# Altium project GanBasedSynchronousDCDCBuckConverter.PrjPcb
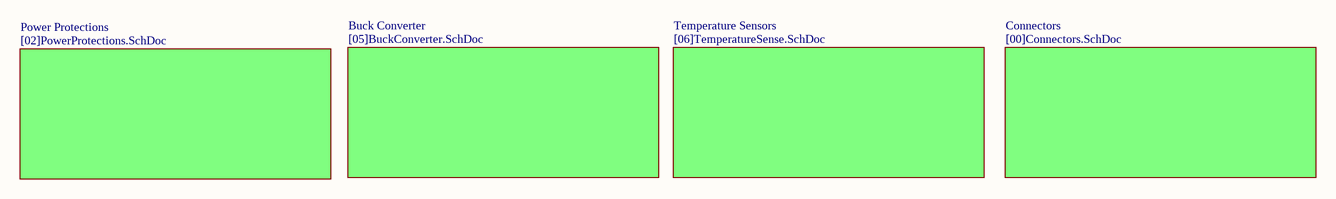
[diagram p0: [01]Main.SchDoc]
5 sheets, 48 parts. Net scope: flat (ports and power ports of the same name join across sheets).
Board file: BuckConverterDesign.PcbDoc
Sheets:
  [01]Main.SchDoc
    Power Protections = [02]PowerProtections.SchDoc
    Buck Converter = [05]BuckConverter.SchDoc
    Temperature Sensors = [06]TemperatureSense.SchDoc
    Connectors = [00]Connectors.SchDoc

## Sheet [01]Main.SchDoc
size A4; SheetNumber: 1; SheetTotal: 5

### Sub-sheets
Buck Converter = [05]BuckConverter.SchDoc: no entries
Connectors = [00]Connectors.SchDoc: no entries
Power Protections = [02]PowerProtections.SchDoc: no entries
Temperature Sensors = [06]TemperatureSense.SchDoc: no entries

## Sheet [02]PowerProtections.SchDoc
size A4; SheetNumber: 2; SheetTotal: 5
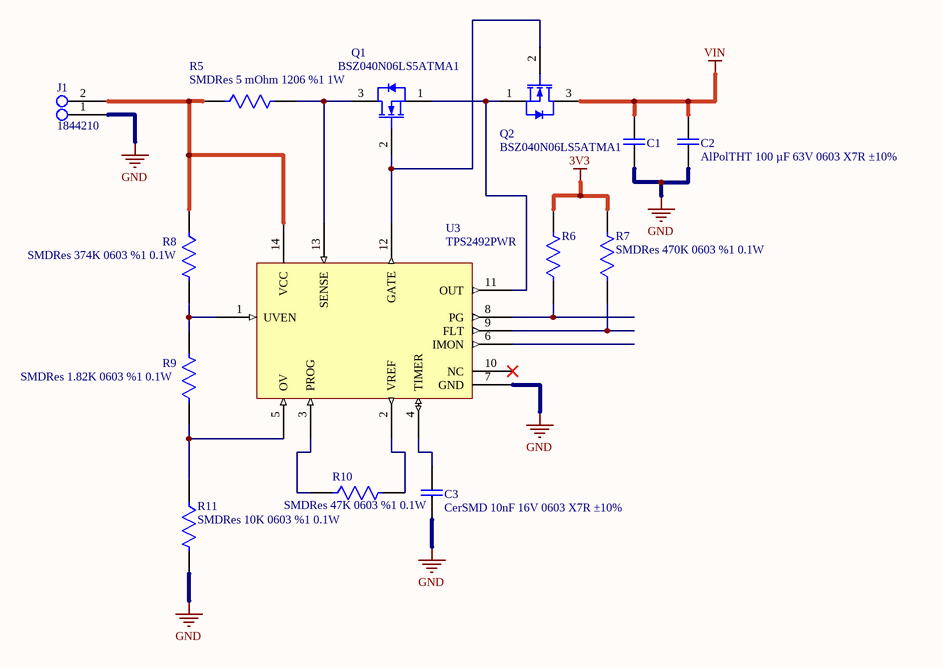
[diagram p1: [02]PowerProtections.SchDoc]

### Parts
C1  AlPolTHT 100 µF 63V 0603 X7R ±10%  [107AVG063MFBJ]  (value not drawn)
C2  AlPolTHT 100 µF 63V 0603 X7R ±10%  [107AVG063MFBJ]
C3  CerSMD 10nF 16V 0603 X7R ±10%  [CAPC1608X09N]
J1  1844210  [1844210]
Q1  BSZ040N06LS5ATMA1  [PG-TSDSON-8-FL]
Q2  BSZ040N06LS5ATMA1  [PG-TSDSON-8-FL]
R5  SMDRes 5 mOhm 1206 %1 1W  [RESC3116X10N]
R6  SMDRes 470K 0603 %1 0.1W  [RESC1508X06N]  (value not drawn)
R7  SMDRes 470K 0603 %1 0.1W  [RESC1508X06N]
R8  SMDRes 374K 0603 %1 0.1W  [RESC1508X06N]
R9  SMDRes 1.82K 0603 %1 0.1W  [RESC1508X06N]
R10  SMDRes 47K 0603 %1 0.1W  [RESC1508X06N]
R11  SMDRes 10K 0603 %1 0.1W  [RESC1508X06N]
U3  TPS2492PWR  [TSOP65P640X120-14L]

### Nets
3V3: R6.2 R7.2
GND: C1.2 C2.2 C3.2 J1.1 R11.2 U3.7(GND)
VIN: C1.1 C2.1 Q2.3(D)
NetC3_1: C3.1 U3.4(TIMER)
NetJ1_2: J1.2 R5.1 R8.1 U3.14(VCC)
NetQ1_1: Q1.1(S) Q2.1(S) U3.11(OUT)
NetQ1_2: Q1.2(G) Q2.2(G) U3.12(GATE)
NetQ1_3: Q1.3(D) R5.2 U3.13(SENSE)
NetR6_1: R6.1 U3.8(PG)
NetR7_1: R7.1 U3.9(FLT)
NetR8_2: R8.2 R9.2 U3.1(UVEN)
NetR9_1: R9.1 R11.1 U3.5(OV)
NetR10_1: R10.1 U3.3(PROG)
NetR10_2: R10.2 U3.2(VREF)

Not connected (* = marked no-connect by the designer): U3 6(IMON) 10(NC)*

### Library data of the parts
C1 C2 = CMP-00002-4: Ceramic Capacitor SMD 100 µF 63V 0603 X7R ±10%; Manufacturer: Cornell Dubilier Knowles
C3 = CMP-00001-3: Ceramic Capacitor SMD  10nF 16V 0603 X7R ±10%; Manufacturer Number: CL10B103KO8WPNC; Manufacturer: Samsung Electro-Mechanics
J1 = CMP-00023-1: 12A 2-Pos, Right Angle
Q1 Q2 = CMP-00004-1: N-MOS 60V 17A (Ta) 101A (Tc)
R5 = CMP-00007-2: 5 mOhms ±1% 1W Chip Resistor 1206 (3216 Metric) Automotive AEC-Q200, Current Sense, Moisture Resistant Metal Foil; Manufacturer Number: CSRF1206FT5L00; Manufacturer: Stackpole Electronics Inc
R6 R7 = CMP-00006-1: Res Thick Film 0603 470K Ohm 1% 0.1W(1/10W) ±100ppm/C Pad SMD T/R Automotive AEC-Q200; Manufacturer: Stackpole Electronics Inc; Manufacturer Number: RMCF0603FT470K
R8 = CMP-00005-2: Res Thick Film 0603 374K Ohm 1% 0.1W(1/10W) ±100ppm/C Pad SMD T/R Automotive AEC-Q200; Manufacturer: Stackpole Electronics Inc; Manufacturer Number: RMCF0603FT374K
R9 = CMP-00003-2: Res Thick Film 0603 1.82K Ohm 1% 0.1W(1/10W) ±100ppm/C Pad SMD T/R Automotive AEC-Q200; Manufacturer: Stackpole Electronics Inc; Manufacturer Number: RMCF0603FT1K82
R10 = CMP-00008-1: Res Thick Film 0603 47K Ohm 1% 0.1W(1/10W) ±100ppm/C Pad SMD T/R Automotive AEC-Q200; Manufacturer Number: RMCF0603FT47K0; Manufacturer: Stackpole Electronics Inc
R11 = CMP-00001-1-1: Res Thick Film 0603 10K Ohm 1% 0.1W(1/10W) ±100ppm/C Pad SMD T/R Automotive AEC-Q200; Manufacturer Number: RMCF0603FT10K0; Manufacturer: Stackpole Electronics Inc
U3 = CMP-00000-1: eFuses - External MOSFETs - 9V-80V; Manufacturer: Texas Instruments; Temperature Rating: -40°C up to 125°C; Voltage Rating: 9V up to 80V; Internal Switch(s): No

## Sheet [05]BuckConverter.SchDoc
size A4; SheetNumber: 3; SheetTotal: 5
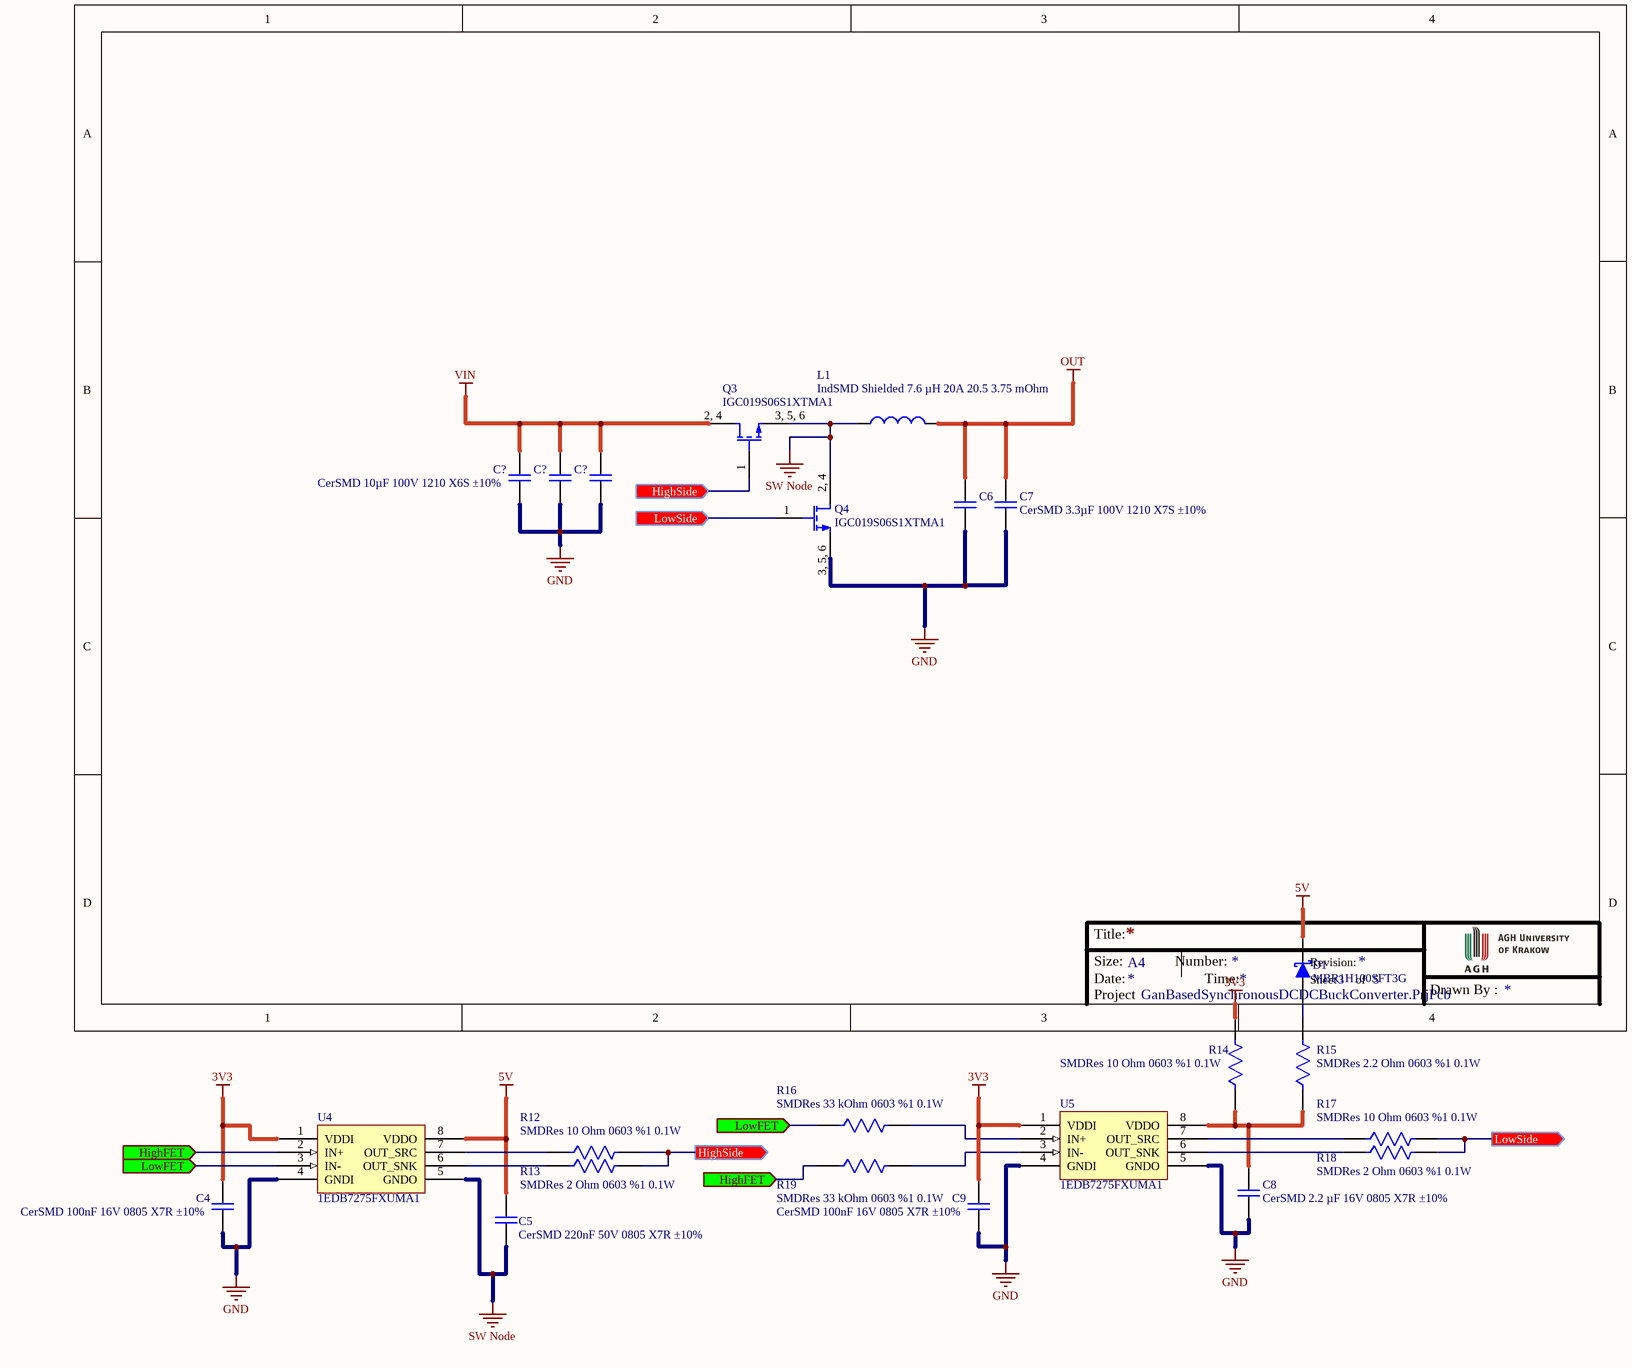
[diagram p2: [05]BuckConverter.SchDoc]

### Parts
(Parts that share a designator on the sheet are numbered #1, #2 ... from top to bottom, then left to right.)
C4  CerSMD 100nF 16V 0805 X7R ±10%  [CAPC2012X09N]
C5  CerSMD 220nF 50V 0805 X7R ±10%  [CAPC2012X09N]
C6  CerSMD 3.3µF 100V 1210 X7S ±10%  [CAPC3225X28N]  (value not drawn)
C7  CerSMD 3.3µF 100V 1210 X7S ±10%  [CAPC3225X28N]
C8  CerSMD 2.2 µF 16V 0805 X7R ±10%  [CAPC2012X09N]
C9  CerSMD 100nF 16V 0805 X7R ±10%  [CAPC2012X09N]
C?#1  CerSMD 10µF 100V 1210 X6S ±10%  [CAPC3216X18N]
C?#2  CerSMD 10µF 100V 1210 X6S ±10%  [CAPC3216X18N]  (value not drawn)
C?#3  CerSMD 10µF 100V 1210 X6S ±10%  [CAPC3216X18N]  (value not drawn)
D1  MBR1H100SFT3G  [SODFL360X95-2N]
L1  IndSMD Shielded 7.6 µH 20A 20.5 3.75 mOhm  [7443557760]
Q3  IGC019S06S1XTMA1  [IGC019S06S1XTMA1]
Q4  IGC019S06S1XTMA1  [IGC019S06S1XTMA1]
R12  SMDRes 10 Ohm 0603 %1 0.1W  [RESC1508X06N]
R13  SMDRes 2 Ohm 0603 %1 0.1W  [RESC1508X06N]
R14  SMDRes 10 Ohm 0603 %1 0.1W  [RESC1508X06N]
R15  SMDRes 2.2 Ohm 0603 %1 0.1W  [RESC1508X06N]
R16  SMDRes 33 kOhm 0603 %1 0.1W  [RESC1508X06N]
R17  SMDRes 10 Ohm 0603 %1 0.1W  [RESC1508X06N]
R18  SMDRes 2 Ohm 0603 %1 0.1W  [RESC1508X06N]
R19  SMDRes 33 kOhm 0603 %1 0.1W  [RESC1508X06N]
U4  1EDB7275FXUMA1  [SOIC127P600X175-8N]
U5  1EDB7275FXUMA1  [SOIC127P600X175-8N]

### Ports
HighFET (in, see [00]Connectors[2B], [00]Connectors[3B], [05]BuckConverter[1E]), HighFET (in, see [00]Connectors[2B], [00]Connectors[3B], [05]BuckConverter[2E]), HighSide (in, see [05]BuckConverter[2E]), HighSide (out, see [05]BuckConverter[2B]), LowFET (in, see [00]Connectors[2B], [00]Connectors[3B], [05]BuckConverter[1E]), LowFET (in, see [00]Connectors[2B], [00]Connectors[3B], [05]BuckConverter[2E]), LowSide (in, see [05]BuckConverter[4E]), LowSide (out, see [05]BuckConverter[2C])

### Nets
3V3: C4.1 C9.1 R14.2 U4.1(VDDI) U5.1(VDDI)
5V: C5.1 D1.2(K) U4.8(VDDO)
GND: C4.2 C6.2 C7.2 C8.2 C9.2 C?#1.2 C?#2.2 C?#3.2 Q4.3,_5,_6(S) U4.4(GNDI) U5.4(GNDI) U5.5(GNDO)
OUT: C6.1 C7.1 L1.2
SW Node: C5.2 L1.1 Q3.3,_5,_6(S) Q4.2,_4(D) U4.5(GNDO)
VIN: C?#1.1 C?#2.1 C?#3.1 Q3.2,_4(D)
NetC8_1: C8.1 R14.1 R15.1 U5.8(VDDO)
NetD1_1: D1.1(A) R15.2
NetJ2_1: R16.1 U4.3(IN-) ; port LowFET
NetJ3_1: R19.1 U4.2(IN+) ; port HighFET
NetQ3_1: Q3.1(G) R12.2 R13.2 ; port HighSide
NetQ4_1: Q4.1(G) R17.2 R18.2 ; port LowSide
NetR12_1: R12.1 U4.7(OUT_SRC)
NetR13_1: R13.1 U4.6(OUT_SNK)
NetR16_2: R16.2 U5.2(IN+)
NetR17_1: R17.1 U5.7(OUT_SRC)
NetR18_1: R18.1 U5.6(OUT_SNK)
NetR19_2: R19.2 U5.3(IN-)

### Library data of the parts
C4 C9 = CMP-00013-1: Ceramic Capacitor SMD 100nF 10V 0805 X7R ±10%; Manufacturer Number: 885012207016; Manufacturer: Würth Elektronik
C5 = CMP-00016-1: Ceramic Capacitor SMD 220nF 50V 0805 X7R ±10%; Manufacturer: Murata Electronics; Manufacturer Number: GRM21BR71H224KA01L; Voltage: 10V
C6 C7 = CMP-00010-1: Ceramic Capacitor SMD 3.3µF 100V 1210 X7S ±10%; Manufacturer: Samsung Electro-Mechanics; Manufacturer Number: C3225X7S2A335K200AB; Voltage: 16V; Temperature Coefficient: X7R
C8 = CMP-00014-1: Ceramic Capacitor SMD 2.2 µF 16V 0805 X7R ±10%; Manufacturer Number: C2012X7R1C225K125AB; Manufacturer: TDK Corporation
C?#1-C?#3 = CMP-000078-1: Ceramic Capacitor SMD 10µF 100V 1210 X6S ±10%; Manufacturer: TDK Corporation; Manufacturer Number: C3216X6S2A106K160AC; Temperature Coefficient: X7R; Voltage: 16V
D1 = CMP-00020-2
L1 = CMP-00011-1: Inductor SMD Shielded 7.6 µH 20A 20.5 3.75 mOhm
Q3 Q4 = CMP-00009-4: GaNFET N-Ch - 60V - 27A (Ta), 99A (Tc); Manufacturer: Infineon Technologies; Vgs(max): ±6.5V; Rdson: 1.9mOhm; Vgs(th): 2.9V; Drive Voltage: 5V; FET Type: N-Channel
R12 R14 R17 = CMP-00017-1: Res Thick Film 0603 10 Ohm Ohm 1% 0.1W(1/10W) ±100ppm/C Pad SMD T/R Automotive AEC-Q200; Manufacturer Number: RMCF0603FT10R0; Manufacturer: Stackpole Electronics Inc
R13 R18 = CMP-00019-1: Res Thick Film 0603 2 Ohm Ohm 1% 0.1W(1/10W) ±100ppm/C Pad SMD T/R Automotive AEC-Q200; Manufacturer: Stackpole Electronics Inc; Manufacturer Number: RMCF0603FT2R00
R15 = CMP-00015-1: Res Thick Film 0603 2.2 Ohm Ohm 1% 0.1W(1/10W) ±100ppm/C Pad SMD T/R Automotive AEC-Q200; Manufacturer Number: RMCF0603FT2R20; Manufacturer: Stackpole Electronics Inc
R16 R19 = CMP-00018-1: Res Thick Film 0603 33 kOhm Ohm 1% 0.1W(1/10W) ±100ppm/C Pad SMD T/R Automotive AEC-Q200; Manufacturer: Stackpole Electronics Inc; Manufacturer Number: RMCF0603FT33K0
U4 U5 = CMP-00012-1

## Sheet [06]TemperatureSense.SchDoc
size A4; SheetNumber: 4; SheetTotal: 5
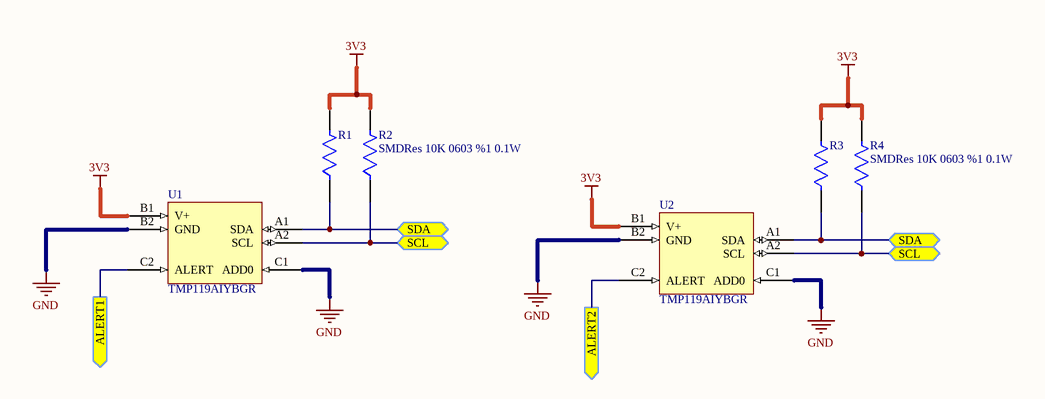
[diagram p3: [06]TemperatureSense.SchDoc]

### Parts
R1  SMDRes 10K 0603 %1 0.1W  [RESC1508X06N]  (value not drawn)
R2  SMDRes 10K 0603 %1 0.1W  [RESC1508X06N]
R3  SMDRes 10K 0603 %1 0.1W  [RESC1508X06N]  (value not drawn)
R4  SMDRes 10K 0603 %1 0.1W  [RESC1508X06N]
U1  TMP119AIYBGR  [BGA6C40P2X3_95X149X52]
U2  TMP119AIYBGR  [BGA6C40P2X3_95X149X52]

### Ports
ALERT1 (out), ALERT2 (out), SCL (bidir, see [00]Connectors[2B], [06]TemperatureSense[2C]), SCL (bidir, see [00]Connectors[2B], [06]TemperatureSense[4C]), SDA (bidir, see [00]Connectors[2B], [06]TemperatureSense[2B]), SDA (bidir, see [00]Connectors[2B], [06]TemperatureSense[4C])

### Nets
3V3: R1.2 R2.2 R3.2 R4.2 U1.B1(V+) U2.B1(V+)
GND: U1.B2(GND) U1.C1(ADD0) U2.B2(GND) U2.C1(ADD0)
NetP1_2: R1.1 R3.1 U1.A1(SDA) U2.A1(SDA) ; port SDA
NetP1_4: R2.1 R4.1 U1.A2(SCL) U2.A2(SCL) ; port SCL
NetU1_C2: U1.C2(ALERT) ; port ALERT1
NetU2_C2: U2.C2(ALERT) ; port ALERT2

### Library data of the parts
R1-R4 = CMP-00001-1-2: Res Thick Film 0603 10K Ohm 1% 0.1W(1/10W) ±100ppm/C Pad SMD T/R Automotive AEC-Q200; Manufacturer Number: RMCF0603FT10K0; Manufacturer: Stackpole Electronics Inc
U1 U2 = CMP-00021-1: Temperature Sensor

## Sheet [00]Connectors.SchDoc
size A4; SheetNumber: 5; SheetTotal: 5
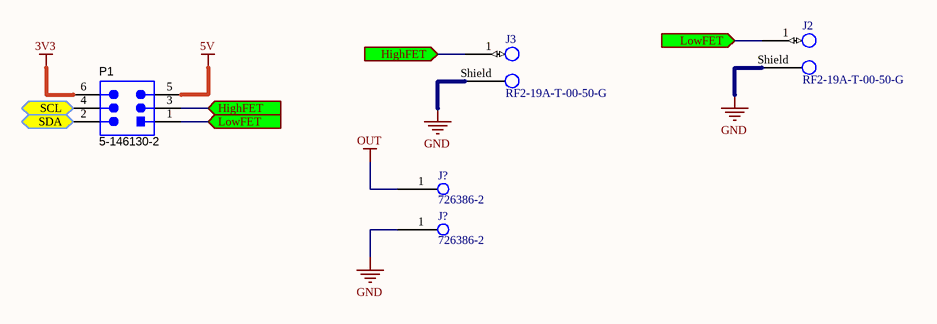
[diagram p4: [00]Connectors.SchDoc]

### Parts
(Parts that share a designator on the sheet are numbered #1, #2 ... from top to bottom, then left to right.)
J2  RF2-19A-T-00-50-G  [RF2-19A-T-00-50-G]
J3  RF2-19A-T-00-50-G  [RF2-19A-T-00-50-G]
J?#1  726386-2  [1844210]
J?#2  726386-2  [1844210]
P1  5-146130-2  [TECO-5-146130-2_V]

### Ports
HighFET (in, see [00]Connectors[2B], [05]BuckConverter[1E], [05]BuckConverter[2E]), HighFET (in, see [00]Connectors[3B], [05]BuckConverter[1E], [05]BuckConverter[2E]), LowFET (in, see [00]Connectors[2B], [05]BuckConverter[1E], [05]BuckConverter[2E]), LowFET (in, see [00]Connectors[3B], [05]BuckConverter[1E], [05]BuckConverter[2E]), SCL (bidir, see [06]TemperatureSense[2C], [06]TemperatureSense[4C]), SDA (bidir, see [06]TemperatureSense[2B], [06]TemperatureSense[4C])

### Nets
3V3: P1.6
5V: P1.5
GND: J2.Shield J3.Shield J?#2.1
OUT: J?#1.1
NetJ2_1: J2.1 P1.1 ; port LowFET
NetJ3_1: J3.1 P1.3 ; port HighFET
NetP1_2: P1.2 ; port SDA
NetP1_4: P1.4 ; port SCL

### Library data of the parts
J2 J3 = CMP-00025-2: Rf Sma Connector
J?#1 J?#2 = CMP-00026-1
P1 = CMP-002-00018-2: Male Header, Pitch 2.54 mm, 2 x 3 Position, Height 8.13 mm, -65 to 125 degC, RoHS, Tube; Manufacturer: TE Connectivity

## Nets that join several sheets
3V3: [02]PowerProtections (R6.2 R7.2), [05]BuckConverter (5 pins), [06]TemperatureSense (6 pins), [00]Connectors (P1.6)
5V: [05]BuckConverter (C5.1 D1.2 U4.8), [00]Connectors (P1.5)
GND: [02]PowerProtections (6 pins), [05]BuckConverter (12 pins), [06]TemperatureSense (U1.B2 U1.C1 U2.B2 U2.C1), [00]Connectors (J2.Shield J3.Shield J?#2.1)
OUT: [05]BuckConverter (C6.1 C7.1 L1.2), [00]Connectors (J?#1.1)
VIN: [02]PowerProtections (C1.1 C2.1 Q2.3), [05]BuckConverter (C?#1.1 C?#2.1 C?#3.1 Q3.2, 4)
NetJ2_1: [05]BuckConverter (R16.1 U4.3), [00]Connectors (J2.1 P1.1)
NetJ3_1: [05]BuckConverter (R19.1 U4.2), [00]Connectors (J3.1 P1.3)
NetP1_2: [06]TemperatureSense (R1.1 R3.1 U1.A1 U2.A1), [00]Connectors (P1.2)
NetP1_4: [06]TemperatureSense (R2.1 R4.1 U1.A2 U2.A2), [00]Connectors (P1.4)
